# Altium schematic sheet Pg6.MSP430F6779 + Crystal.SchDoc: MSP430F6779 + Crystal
size 431 x 279 mm; Date: Not shown in title block; ApprovedBy: Not shown in title block; CheckedBy: Not shown in title block; Author: Not shown in title block; CompanyName: Not shown in title block; Engineer: Not shown in title block; Organization: Not shown in title block; Address1: Not shown in title block; Address2: Not shown in title block; Address3: Not shown in title block; Address4: Not shown in title block; DocumentNumber: 6; Revision: Use project parameter SCH_Rev; SheetNumber: 6; SheetTotal: 8; PageSetup: Record=PageOptions|CenterHorizontal=True|CenterVertical=True|PrintScale=1.00|XCorrection=1.00|YCorrection=1.00|PrintKind=0|BorderSize=5000000|LeftOffset=0|BottomOffset=0|Orientation=2|PaperLength=1000|PaperWidth=1000|Scale=100|PaperSource=15|PrintQuality=600|MediaType=1|DitherType=10|PaperKind=Letter|PrintScaleMode=1
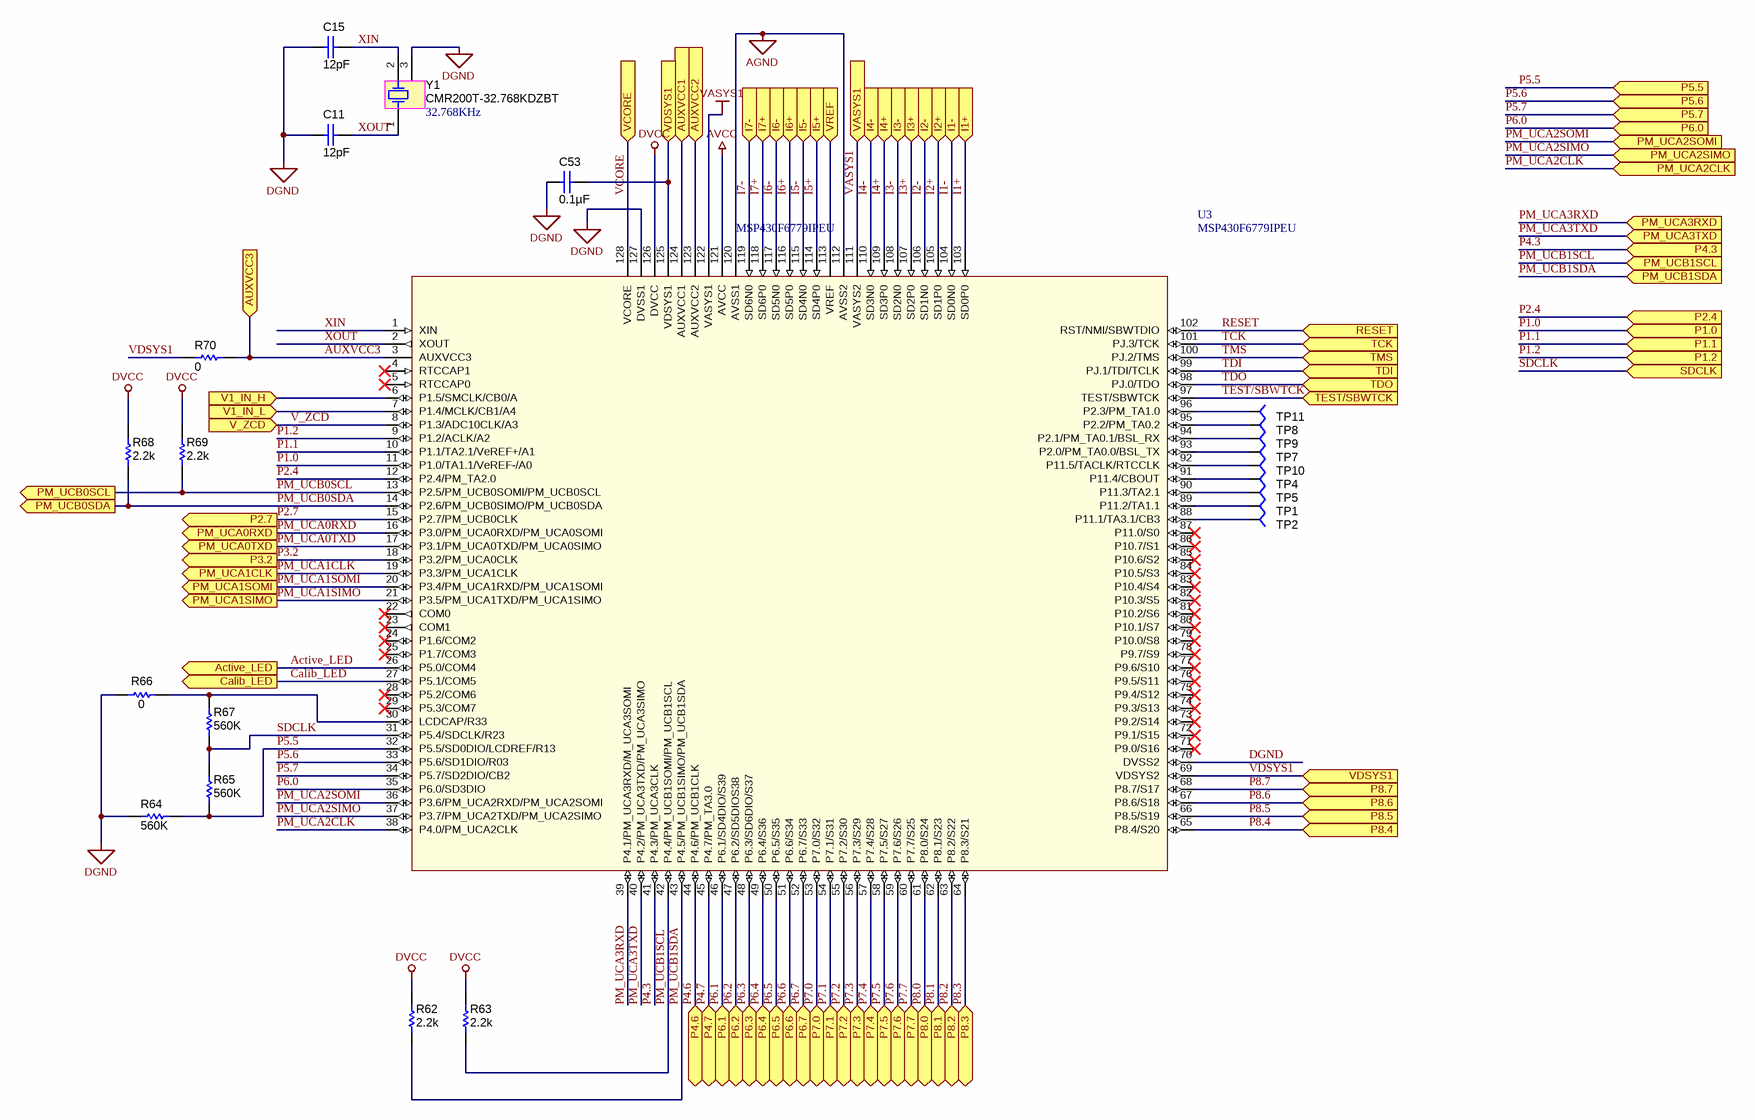
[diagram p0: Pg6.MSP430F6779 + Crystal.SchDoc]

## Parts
C11  ValueDisplayed: 12pF  [0603]  (hidden comment: 06035A120JAT2A)
C15  ValueDisplayed: 12pF  [0603]  (hidden comment: 06035A120JAT2A)
C53  ValueDisplayed: 0.1µF  [0603]  (hidden comment: 06033C104JAT2A)
R62  value 2.2k  [0603]  (hidden comment: CRCW06032K20JNEA)
R63  value 2.2k  [0603]  (hidden comment: CRCW06032K20JNEA)
R64  value 560K  [0603]  (hidden comment: CRCW0603560KFKEA)
R65  value 560K  [0603]  (hidden comment: CRCW0603560KFKEA)
R66  value 0  [0603]  (hidden comment: CRCW06030000Z0EA)
R67  value 560K  [0603]  (hidden comment: CRCW0603560KFKEA)
R68  value 2.2k  [0603]  (hidden comment: CRCW06032K20JNEA)
R69  value 2.2k  [0603]  (hidden comment: CRCW06032K20JNEA)
R70  value 0  [0805_HV]  (hidden comment: CRCW08050000Z0EA)
TP1  TP-040_RND  [TP_25MIL-SMT]  (value not drawn)
TP2  TP-040_RND  [TP_25MIL-SMT]  (value not drawn)
TP4  TP-040_RND  [TP_25MIL-SMT]  (value not drawn)
TP5  TP-040_RND  [TP_25MIL-SMT]  (value not drawn)
TP7  TP-040_RND  [TP_25MIL-SMT]  (value not drawn)
TP8  TP-040_RND  [TP_25MIL-SMT]  (value not drawn)
TP9  TP-040_RND  [TP_25MIL-SMT]  (value not drawn)
TP10  TP-040_RND  [TP_25MIL-SMT]  (value not drawn)
TP11  TP-040_RND  [TP_25MIL-SMT]  (value not drawn)
U3  MSP430F6779IPEU  [QFP50P1600X2200X160-128N]
Y1  CMR200T-32.768KDZBT  Frequency: 32.768KHz  [XTAL_CMR200T]

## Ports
Active_LED (out), AUXVCC1 (in), AUXVCC2 (in), AUXVCC3 (in), Calib_LED (out), I1+ (in), I1- (in), I2+ (in), I2- (in), I3+ (in), I3- (in), I4+ (in), I4- (in), I5+ (in), I5- (in), I6+ (in), I6- (in), I7+ (in), I7- (in), P1.0 (in), P1.1 (in), P1.2 (in), P2.4 (in), P2.7 (out), P3.2 (out), P4.3 (in), P4.6, P4.7, P5.5 (in), P5.6 (in), P5.7 (in), P6.0 (in), P6.1, P6.2, P6.3, P6.4, P6.5, P6.6, P6.7, P7.0, P7.1, P7.2, P7.3, P7.4, P7.5, P7.6, P7.7, P8.0, P8.1, P8.2, P8.3, P8.4 (in), P8.5 (in), P8.6 (in), P8.7 (in), PM_UCA0RXD (out), PM_UCA0TXD (out), PM_UCA1CLK (out), PM_UCA1SIMO (out), PM_UCA1SOMI (out), PM_UCA2CLK (in), PM_UCA2SIMO (in), PM_UCA2SOMI (in), PM_UCA3RXD (in), PM_UCA3TXD (in), PM_UCB0SCL (out), PM_UCB0SDA (out), PM_UCB1SCL (in), PM_UCB1SDA (in), RESET (in), SDCLK (in), TCK (in), TDI (in), TDO (in), TEST/SBWTCK (in), TMS (in), V1_IN_H (in), V1_IN_L (in), V_ZCD (in), VASYS1 (in), VCORE (in), VDSYS1 (in), VREF (in)

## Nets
AGND: U3.112(AVSS2) U3.120(AVSS1)
AVCC: U3.121(AVCC)
DGND: C11.2 C15.2 C53.1 R64.2 R66.1 U3.70(DVSS2) U3.127(DVSS1) Y1.3
DVCC: R62.2 R63.2 R68.2 R69.2 U3.126(DVCC)
VASYS1: U3.111(VASYS2) U3.122(VASYS1) ; port VASYS1
Active_LED: U3.26(P5.0/COM4) ; port Active_LED
AUXVCC1: U3.124(AUXVCC1) ; port AUXVCC1
AUXVCC2: U3.123(AUXVCC2) ; port AUXVCC2
AUXVCC3: R70.2 U3.3(AUXVCC3) ; port AUXVCC3
Calib_LED: U3.27(P5.1/COM5) ; port Calib_LED
I1+: U3.103(SD0P0) ; port I1+
I1-: U3.104(SD0N0) ; port I1-
I2+: U3.105(SD1P0) ; port I2+
I2-: U3.106(SD1N0) ; port I2-
I3+: U3.107(SD2P0) ; port I3+
I3-: U3.108(SD2N0) ; port I3-
I4+: U3.109(SD3P0) ; port I4+
I4-: U3.110(SD3N0) ; port I4-
I5+: U3.114(SD4P0) ; port I5+
I5-: U3.115(SD4N0) ; port I5-
I6+: U3.116(SD5P0) ; port I6+
I6-: U3.117(SD5N0) ; port I6-
I7+: U3.118(SD6P0) ; port I7+
I7-: U3.119(SD6N0) ; port I7-
P1.0: U3.11(P1.0/TA1.1/VeREF-/A0) ; port P1.0
P1.1: U3.10(P1.1/TA2.1/VeREF+/A1) ; port P1.1
P1.2: U3.9(P1.2/ACLK/A2) ; port P1.2
P2.4: U3.12(P2.4/PM_TA2.0) ; port P2.4
P2.7: U3.15(P2.7/PM_UCB0CLK) ; port P2.7
P3.2: U3.18(P3.2/PM_UCA0CLK) ; port P3.2
P4.3: U3.41(P4.3/PM_UCA3CLK) ; port P4.3
P4.6: U3.44(P4.6/PM_UCB1CLK) ; port P4.6
P4.7: U3.45(P4.7/PM_TA3.0) ; port P4.7
P5.5: R64.1 R65.1 U3.32(P5.5/SD0DIO/LCDREF/R13) ; port P5.5
P5.6: U3.33(P5.6/SD1DIO/R03) ; port P5.6
P5.7: U3.34(P5.7/SD2DIO/CB2) ; port P5.7
P6.0: U3.35(P6.0/SD3DIO) ; port P6.0
P6.1: U3.46(P6.1/SD4DIO/S39) ; port P6.1
P6.2: U3.47(P6.2/SD5DIOS38) ; port P6.2
P6.3: U3.48(P6.3/SD6DIO/S37) ; port P6.3
P6.4: U3.49(P6.4/S36) ; port P6.4
P6.5: U3.50(P6.5/S35) ; port P6.5
P6.6: U3.51(P6.6/S34) ; port P6.6
P6.7: U3.52(P6.7/S33) ; port P6.7
P7.0: U3.53(P7.0/S32) ; port P7.0
P7.1: U3.54(P7.1/S31) ; port P7.1
P7.2: U3.55(P7.2/S30) ; port P7.2
P7.3: U3.56(P7.3/S29) ; port P7.3
P7.4: U3.57(P7.4/S28) ; port P7.4
P7.5: U3.58(P7.5/S27) ; port P7.5
P7.6: U3.59(P7.6/S26) ; port P7.6
P7.7: U3.60(P7.7/S25) ; port P7.7
P8.0: U3.61(P8.0/S24) ; port P8.0
P8.1: U3.62(P8.1/S23) ; port P8.1
P8.2: U3.63(P8.2/S22) ; port P8.2
P8.3: U3.64(P8.3/S21) ; port P8.3
P8.4: U3.65(P8.4/S20) ; port P8.4
P8.5: U3.66(P8.5/S19) ; port P8.5
P8.6: U3.67(P8.6/S18) ; port P8.6
P8.7: U3.68(P8.7/S17) ; port P8.7
PM_UCA0RXD: U3.16(P3.0/PM_UCA0RXD/PM_UCA0SOMI) ; port PM_UCA0RXD
PM_UCA0TXD: U3.17(P3.1/PM_UCA0TXD/PM_UCA0SIMO) ; port PM_UCA0TXD
PM_UCA1CLK: U3.19(P3.3/PM_UCA1CLK) ; port PM_UCA1CLK
PM_UCA1SIMO: U3.21(P3.5/PM_UCA1TXD/PM_UCA1SIMO) ; port PM_UCA1SIMO
PM_UCA1SOMI: U3.20(P3.4/PM_UCA1RXD/PM_UCA1SOMI) ; port PM_UCA1SOMI
PM_UCA2CLK: U3.38(P4.0/PM_UCA2CLK) ; port PM_UCA2CLK
PM_UCA2SIMO: U3.37(P3.7/PM_UCA2TXD/PM_UCA2SIMO) ; port PM_UCA2SIMO
PM_UCA2SOMI: U3.36(P3.6/PM_UCA2RXD/PM_UCA2SOMI) ; port PM_UCA2SOMI
PM_UCA3RXD: U3.39(P4.1/PM_UCA3RXD/M_UCA3SOMI) ; port PM_UCA3RXD
PM_UCA3TXD: U3.40(P4.2/PM_UCA3TXD/PM_UCA3SIMO) ; port PM_UCA3TXD
PM_UCB0SCL: R69.1 U3.13(P2.5/PM_UCB0SOMI/PM_UCB0SCL) ; port PM_UCB0SCL
PM_UCB0SDA: R68.1 U3.14(P2.6/PM_UCB0SIMO/PM_UCB0SDA) ; port PM_UCB0SDA
PM_UCB1SCL: R63.1 U3.42(P4.4/PM_UCB1SOMI/PM_UCB1SCL) ; port PM_UCB1SCL
PM_UCB1SDA: R62.1 U3.43(P4.5/PM_UCB1SIMO/PM_UCB1SDA) ; port PM_UCB1SDA
RESET: U3.102(RST/NMI/SBWTDIO) ; port RESET
SDCLK: R65.2 R67.1 U3.31(P5.4/SDCLK/R23) ; port SDCLK
TCK: U3.101(PJ.3/TCK) ; port TCK
TDI: U3.99(PJ.1/TDI/TCLK) ; port TDI
TDO: U3.98(PJ.0/TDO) ; port TDO
TEST/SBWTCK: U3.97(TEST/SBWTCK) ; port TEST/SBWTCK
TMS: U3.100(PJ.2/TMS) ; port TMS
V1_IN_H: U3.6(P1.5/SMCLK/CB0/A) ; port V1_IN_H
V1_IN_L: U3.7(P1.4/MCLK/CB1/A4) ; port V1_IN_L
V_ZCD: U3.8(P1.3/ADC10CLK/A3) ; port V_ZCD
VCORE: U3.128(VCORE) ; port VCORE
VDSYS1: C53.2 R70.1 U3.69(VDSYS2) U3.125(VDSYS1) ; port VDSYS1
VREF: U3.113(VREF) ; port VREF
XIN: C15.1 U3.1(XIN) Y1.2
XOUT: C11.1 U3.2(XOUT) Y1.1
NetR66_2: R66.2 R67.2 U3.30(LCDCAP/R33)
NetTP1_1: TP1.1 U3.89(P11.2/TA1.1)
NetTP2_1: TP2.1 U3.88(P11.1/TA3.1/CB3)
NetTP4_1: TP4.1 U3.91(P11.4/CBOUT)
NetTP5_1: TP5.1 U3.90(P11.3/TA2.1)
NetTP7_1: TP7.1 U3.93(P2.0/PM_TA0.0/BSL_TX)
NetTP8_1: TP8.1 U3.95(P2.2/PM_TA0.2)
NetTP9_1: TP9.1 U3.94(P2.1/PM_TA0.1/BSL_RX)
NetTP10_1: TP10.1 U3.92(P11.5/TACLK/RTCCLK)
NetTP11_1: TP11.1 U3.96(P2.3/PM_TA1.0)

Not connected (* = marked no-connect by the designer): U3 4(RTCCAP1)* 5(RTCCAP0)* 22(COM0)* 23(COM1)* 24(P1.6/COM2)* 25(P1.7/COM3)* 28(P5.2/COM6)* 29(P5.3/COM7)* 71(P9.0/S16)* 72(P9.1/S15)* 73(P9.2/S14)* 74(P9.3/S13)* 75(P9.4/S12)* 76(P9.5/S11)* 77(P9.6/S10)* 78(P9.7/S9)* 79(P10.0/S8)* 80(P10.1/S7)* 81(P10.2/S6)* 82(P10.3/S5)* 83(P10.4/S4)* 84(P10.5/S3)* 85(P10.6/S2)* 86(P10.7/S1)* 87(P11.0/S0)*

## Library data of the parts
C11 C15 = 06035A120JAT2A: CAP, CERM, 12pF, 50V, +/-5%, C0G/NP0, 0603; Manufacturer: AVX; Polarized: N; CompType: Capacitor; U/M: EA; Cap_F: 0.000000000012; Tolerance_%: 5; ESR_Ohm: 0.363; Value1: 0.363 ohm; VDC_V: 50; TaMin_C: -55; TaMax_C: 125
C53 = 06033C104JAT2A: CAP, CERM, 0.1uF, 25V, +/-5%, X7R, 0603; Manufacturer: AVX; Polarized: N; CompType: Capacitor; U/M: EA; Cap_F: 0.0000001; Tolerance_%: 5; ESR_Ohm: 0.05; Value1: 0.05 ohm; VDC_V: 25; TaMin_C: -55; TaMax_C: 125
R62 R63 R68 R69 = CRCW06032K20JNEA: RES, 2.2k ohm, 5%, 0.1W, 0603; Manufacturer: Vishay-Dale; CompType: Resistor; Res_ohm: 2200; Value_Code: 2k20; Tolerance_%: 5; Power_W: 0.1; VDC_V: 75; TempCo: 200 ppm/C; EIA_Code: E24; U/M: EA
R64 R65 R67 = CRCW06032K20JNEA: RES 560K OHM 1/10W 1% 0603 SMD; Manufacturer: Vishay-Dale; CompType: Resistor; Tolerance_%: 1; Power_W: 0.1; Value2: 0.1W; VDC_V: 75; TempCo: 100 ppm/C; EIA_Code: E24; U/M: EA
R66 = CRCW08050000Z0EA: RES 0.0 OHM 1/10W JUMP 0603 SMD; Manufacturer: Vishay-Dale; CompType: Resistor; Value_Code: 0000; Tolerance_%: 5; Power_W: 0.125; Value2: 0.1W; VDC_V: 150; EIA_Code: E24; U/M: EA
R70 = CRCW0805330KJNEA: RES, 0 ohm, 5%, 0.125W, 0805; Manufacturer: Vishay-Dale; CompType: Resistor; Tolerance_%: 5; Power_W: 0.125; VDC_V: 150; TempCo: 200 ppm/C; EIA_Code: E24; U/M: EA
TP1 TP2 TP4 TP5 TP7-TP11 = TP-040_RND: Test Point, O.040 Hole; Manufacturer: STD; Value: STD
U3 = MSP430F6779IPEU: IC, MCU 16BIT 512KB FLASH, LQFP-128; Manufacturer: TEXAS INSTRUMENTS; SymbolCreator: x0199378
Y1 = CMR200T-32.768KDZBT: CRYSTAL, 32.768KHz, 6PF, +/- 20PPM, SMD-3P; Manufacturer: CITIZEN; SymbolCreator: x0199378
